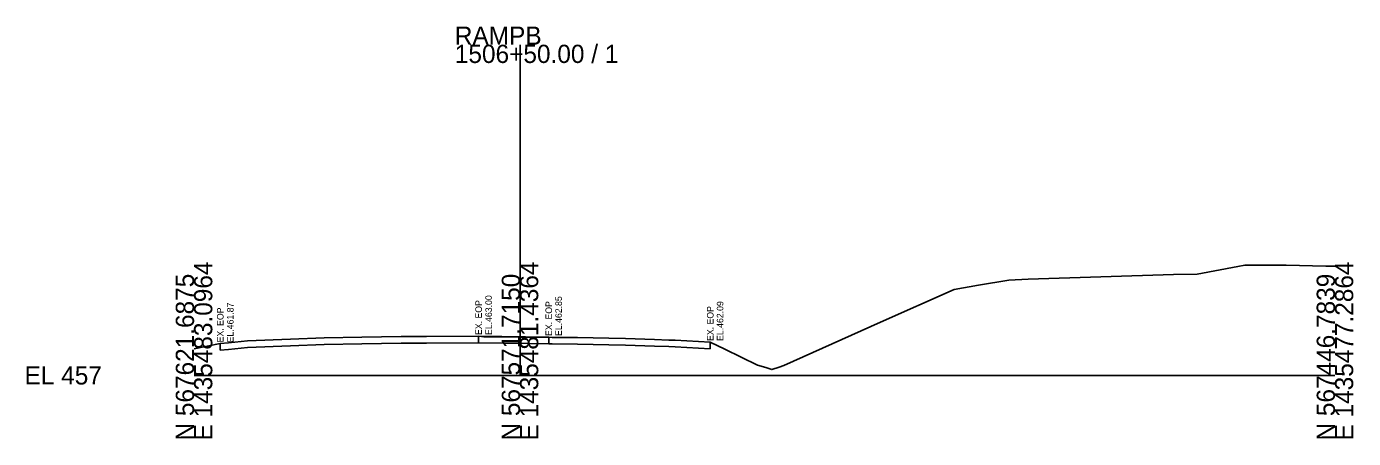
# Model space of a CAD drawing. Extents: x 1431908 to 1449087, y 567604 to 577825.
# Drawn here: x 1440484.4 to 1440688, y 573048.6 to 573111.9 of the extents above; entities that cross this region are included whole.
import ezdxf

# ---------------------------------------------------------------- set-up
doc = ezdxf.new("R2010")
doc.units = 0
for name, color, linetype in [('DESIGN - SHEET - Light Grid', 7, 'Continuous'), ('DESIGN - TYPICAL - Finished Grade and Subgrade', 7, 'Continuous'), ('SURVEY - GROUND - Existing Pavement Layer', 7, 'Continuous'), ('SURVEY - GROUND - Existing Pavement Text', 7, 'Continuous'), ('SURVEY - GROUND - Top of Ground', 7, 'Continuous')]:
    doc.layers.add(name, color=color, linetype=linetype)

msp = doc.modelspace()

# ---------------------------------------------------------------- linework, layer by layer
at = {"layer": 'DESIGN - SHEET - Light Grid'}
for p, q in [((1440560.12, 573058.33), (1440560.12, 573109.1)), ((1440510.12, 573058.33), (1440560.12, 573058.33)), ((1440560.12, 573058.33), (1440685.12, 573058.33))]:
    msp.add_line(p, q, dxfattribs=at)
at = {"layer": 'DESIGN - TYPICAL - Finished Grade and Subgrade'}
for p, q in [((1440564.53, 573064.18), (1440553.77, 573064.33)), ((1440553.77, 573063.33), (1440565.03, 573063.17))]:
    msp.add_line(p, q, dxfattribs=at)
at = {"layer": 'SURVEY - GROUND - Existing Pavement Layer'}
for p, q in [((1440514.14, 573062.2), (1440514.14, 573063.2)), ((1440514.14, 573062.2), (1440515.42, 573062.32)), ((1440515.42, 573062.32), (1440518.34, 573062.62)), ((1440518.34, 573062.62), (1440524.92, 573062.88)), ((1440524.92, 573062.88), (1440530.09, 573063.09)), ((1440530.09, 573063.09), (1440535.88, 573063.18)), ((1440535.88, 573063.18), (1440541.88, 573063.28)), ((1440541.88, 573063.28), (1440545.8, 573063.29)), ((1440545.8, 573063.29), (1440553.77, 573063.33)), ((1440553.77, 573064.33), (1440553.77, 573063.33)), ((1440564.53, 573063.18), (1440564.53, 573064.18)), ((1440564.53, 573063.18), (1440565.03, 573063.17)), ((1440565.03, 573063.17), (1440568.92, 573063.13)), ((1440568.92, 573063.13), (1440573.76, 573063.04)), ((1440573.76, 573063.04), (1440576.3, 573062.98)), ((1440576.3, 573062.98), (1440580.77, 573062.83)), ((1440580.77, 573062.83), (1440582.96, 573062.76)), ((1440582.96, 573062.76), (1440583.92, 573062.73)), ((1440583.92, 573062.73), (1440589.3, 573062.42)), ((1440589.3, 573063.42), (1440589.3, 573062.42))]:
    msp.add_line(p, q, dxfattribs=at)
at = {"layer": 'SURVEY - GROUND - Top of Ground'}
msp.add_lwpolyline([(1440510.12, 573062.42), (1440514.14, 573063.2), (1440515.42, 573063.32), (1440518.34, 573063.62), (1440524.92, 573063.88), (1440530.09, 573064.09), (1440535.88, 573064.18), (1440541.88, 573064.28), (1440545.8, 573064.29), (1440553.77, 573064.33), (1440554.19, 573064.29), (1440554.58, 573064.25), (1440560.12, 573064.21), (1440563.27, 573064.2), (1440564.53, 573064.18), (1440565.03, 573064.17), (1440568.92, 573064.13), (1440573.76, 573064.04), (1440576.3, 573063.98), (1440580.77, 573063.83), (1440582.96, 573063.76), (1440583.92, 573063.73), (1440589.3, 573063.42), (1440591.54, 573062.36), (1440596.57, 573059.9), (1440597.81, 573059.53), (1440598.76, 573059.22), (1440599.86, 573059.61), (1440600.57, 573059.87), (1440615.41, 573066.48), (1440626.74, 573071.5), (1440630.44, 573072.16), (1440635.1, 573072.97), (1440638.08, 573073.09), (1440660.37, 573073.84), (1440664.01, 573073.88), (1440670.24, 573075.05), (1440671.31, 573075.25), (1440673.67, 573075.25), (1440677.64, 573075.24), (1440683.74, 573075.12), (1440684.17, 573075.12), (1440685.12, 573075.09)], dxfattribs=at)

# ---------------------------------------------------------------- texts
at = {"layer": 'DESIGN - SHEET - Light Grid'}
for s, p in [('RAMPB', (1440550.12, 573109.1)), ('1506+50.00 / 1', (1440550.12, 573106.3)), ('EL 457', (1440484.12, 573056.93))]:
    msp.add_text(s, height=2.8, dxfattribs=at).set_placement(p)
for s, p in [('E 1435483.0964', (1440512.92, 573048.33)), ('E 1435481.4364', (1440562.92, 573048.33)), ('E 1435477.2864', (1440687.92, 573048.33)), ('N 567621.6875', (1440510.12, 573048.33)), ('N 567571.7150', (1440560.12, 573048.33)), ('N 567446.7839', (1440685.12, 573048.33))]:
    msp.add_text(s, height=2.8, rotation=90, dxfattribs=at).set_placement(p)
at = {"layer": 'SURVEY - GROUND - Existing Pavement Text'}
for s, p in [('EL.463.00', (1440555.81, 573064.53)), ('EX. EOP', (1440514.64, 573063.4)), ('EL.461.87', (1440516.18, 573063.4)), ('EX. EOP', (1440554.27, 573064.53)), ('EX. EOP', (1440565.03, 573064.38)), ('EL.462.85', (1440566.54, 573064.38)), ('EX. EOP', (1440589.8, 573063.62)), ('EL.462.09', (1440591.31, 573063.62))]:
    msp.add_text(s, height=1, rotation=90, dxfattribs=at).set_placement(p)

doc.saveas('drawing.dxf')
